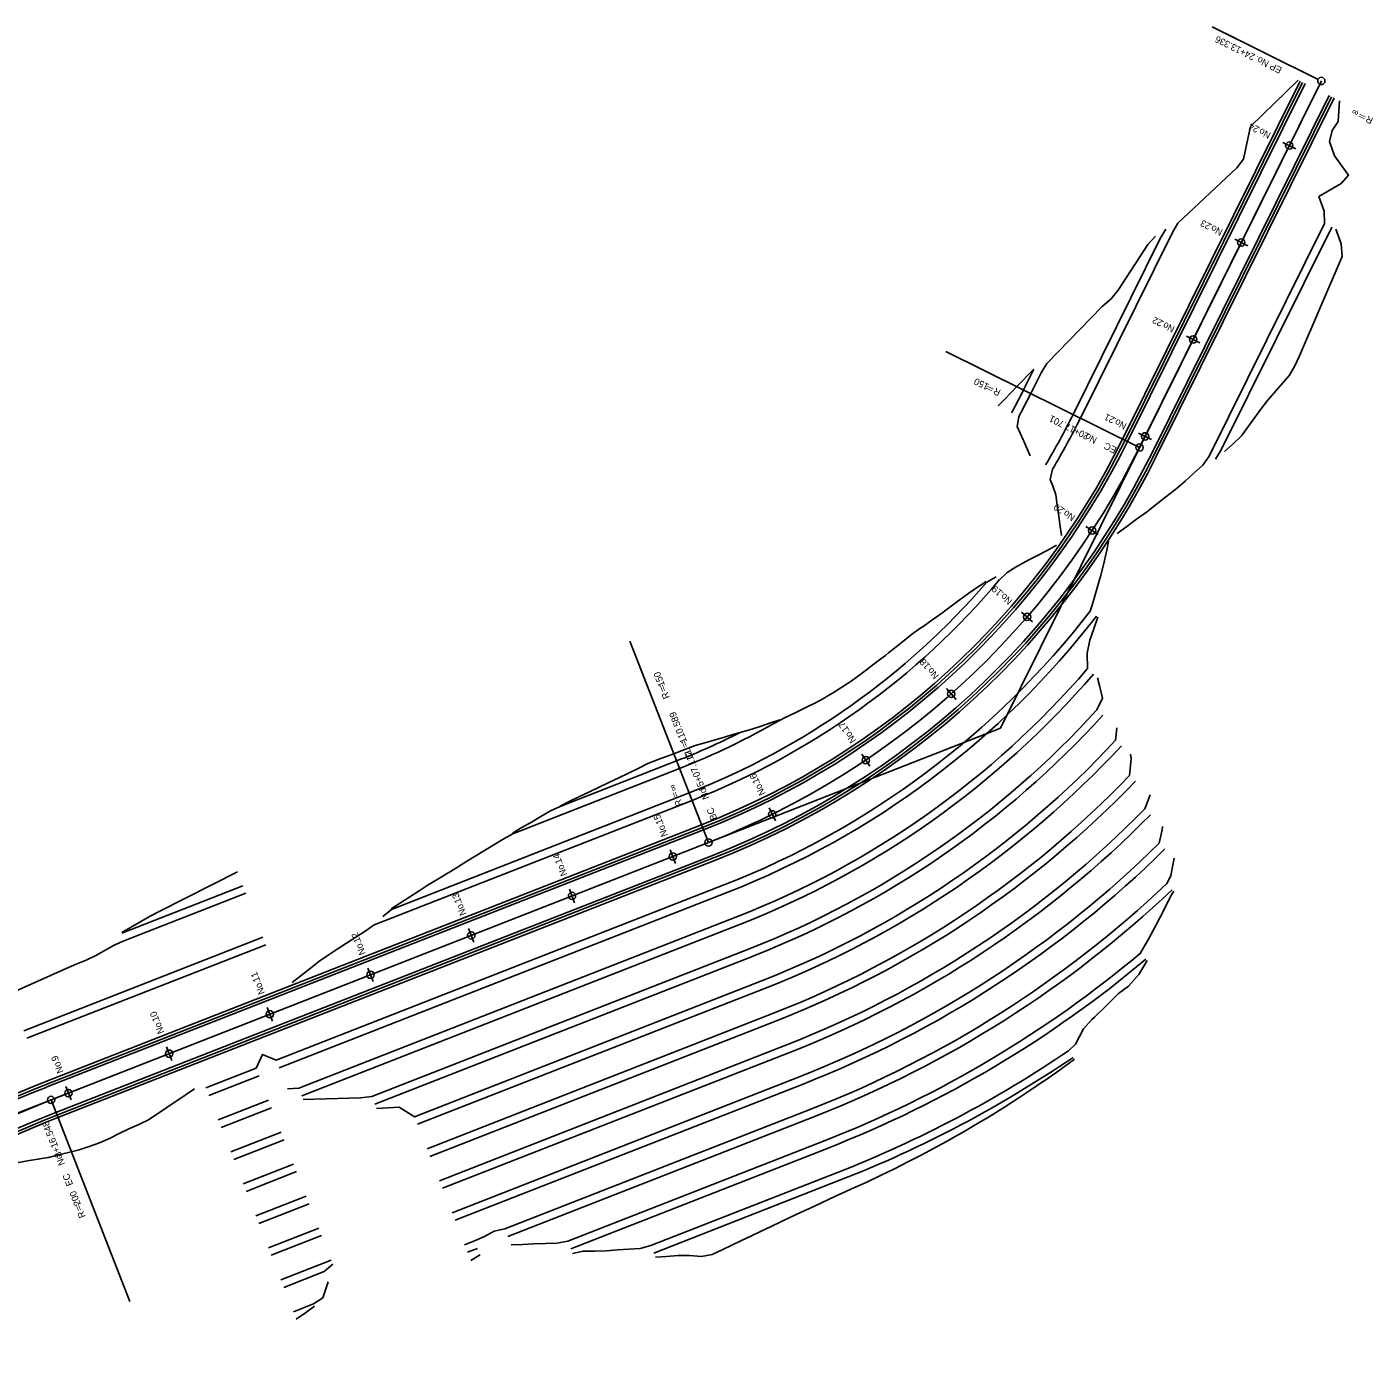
# Model space of a CAD drawing. Extents: x 46571 to 46965, y 10697 to 11034.
# Drawn here: x 46716.5 to 46965.4, y 10784.8 to 11033.7 of the extents above; entities that cross this region are included whole.
import ezdxf

# ---------------------------------------------------------------- set-up
doc = ezdxf.new("R2010")
doc.units = 0
for name, color, linetype in [('Default', 7, 'Continuous'), ('作業レイヤ1', 7, 'Continuous'), ('地形_主曲線_等高線', 7, 'Continuous'), ('地形_土崖 コンクリート、堅固な石積等斜面（地理院地図Vector）', 7, 'Continuous'), ('建物_普通建物_普通建物（地理院地図Vector）', 7, 'Continuous'), ('建物_普通建物_普通建物（外周線）（地理院地図Vector）', 7, 'Continuous'), ('河川_通常部（地理院地図Vector）', 7, 'Continuous'), ('現況_地形_三角形', 7, 'Continuous'), ('等高線等深線_等高線_主曲線通常部（地理院地図Vector）', 7, 'Continuous'), ('道路_通常部_通常部（地理院地図Vector）', 7, 'Continuous')]:
    doc.layers.add(name, color=color, linetype=linetype)

msp = doc.modelspace()

# ---------------------------------------------------------------- linework, layer by layer
at = {"layer": 'Default'}
for p, q in [((46955.22, 11024.01), (46935.66, 11033.7)), ((46935.66, 11033.7), (46940.14, 11031.48)), ((46896.47, 10904.04), (46955.82, 11023.71)), ((46922.21, 10955.95), (46955.82, 11023.71)), ((46955.82, 11023.71), (46955.82, 11023.71)), ((46949.89, 11011.76), (46949.89, 11011.76)), ((46941.01, 10993.84), (46941.01, 10993.84)), ((46932.12, 10975.92), (46932.12, 10975.92)), ((46922.21, 10955.95), (46886.38, 10973.72)), ((46923.23, 10958.01), (46923.23, 10958.01)), ((46922.21, 10955.95), (46922.21, 10955.95)), ((46913.43, 10940.59), (46913.43, 10940.59)), ((46901.41, 10924.62), (46901.41, 10924.62)), ((46842.51, 10882.92), (46827.93, 10920.17)), ((46887.38, 10910.39), (46887.38, 10910.39)), ((46679.76, 10819.21), (46896.47, 10904.04)), ((46871.58, 10898.15), (46871.58, 10898.15)), ((46854.29, 10888.13), (46854.29, 10888.13)), ((46720.93, 10835.33), (46842.51, 10882.92)), ((46842.51, 10882.92), (46842.51, 10882.92)), ((46835.89, 10880.33), (46835.89, 10880.33)), ((46817.26, 10873.04), (46817.26, 10873.04)), ((46798.64, 10865.75), (46798.64, 10865.75)), ((46780.01, 10858.46), (46780.01, 10858.46)), ((46761.39, 10851.17), (46761.39, 10851.17)), ((46742.77, 10843.88), (46742.77, 10843.88)), ((46720.93, 10835.33), (46720.93, 10835.33)), ((46720.93, 10835.33), (46735.51, 10798.08)), ((46724.14, 10836.59), (46724.14, 10836.59))]:
    msp.add_line(p, q, dxfattribs=at)
for centre in [(46955.82, 11023.71), (46949.89, 11011.76), (46941.01, 10993.84), (46932.12, 10975.92), (46923.23, 10958.01), (46922.21, 10955.95), (46913.43, 10940.59), (46901.41, 10924.62), (46887.38, 10910.39), (46871.58, 10898.15), (46854.29, 10888.13), (46842.51, 10882.92), (46835.89, 10880.33), (46817.26, 10873.04), (46798.64, 10865.75), (46780.01, 10858.46), (46761.39, 10851.17), (46742.77, 10843.88), (46720.93, 10835.33), (46724.14, 10836.59)]:
    msp.add_circle(centre, 0.675, dxfattribs=at)
for centre, radius, start, end in [((46787.83, 11022.6), 150, 291.3768, 333.6189), ((46787.83, 11022.6), 150, 291.3768, 333.6189), ((46793.83, 10649.09), 200, 111.3768, 136.3054), ((46793.83, 10649.09), 200, 111.3768, 136.3054)]:
    msp.add_arc(centre, radius, start, end, dxfattribs=at)
at = {"layer": '作業レイヤ1'}
for p, q in [((46922.21, 10955.95), (46955.82, 11023.71)), ((46720.93, 10835.33), (46842.51, 10882.92))]:
    msp.add_line(p, q, dxfattribs=at)
for centre, radius, start, end in [((46787.83, 11022.6), 150, 291.3768, 333.6189), ((46793.83, 10649.09), 200, 111.3768, 136.3054)]:
    msp.add_arc(centre, radius, start, end, dxfattribs=at)
at = {"layer": '地形_主曲線_等高線'}
for p, q in [((46900.75, 10966.59), (46902.66, 10970.45)), ((46734.03, 10866.19), (46756.38, 10874.94)), ((46715.92, 10848.11), (46760.11, 10865.41)), ((46716.47, 10846.72), (46760.66, 10864.01))]:
    msp.add_line(p, q, dxfattribs=at)
for points in [[(46911.26, 10961.38), (46928.27, 10995.69), (46929.31, 10997.41), (46940.19, 11007.64), (46941.42, 11009.27), (46942.28, 11013.3), (46942.72, 11015.32), (46951.52, 11023.87)], [(46918.04, 10940.04), (46919.19, 10940.86), (46919.85, 10941.34), (46921.65, 10942.67), (46923.46, 10944.02), (46925.27, 10945.4), (46927.08, 10946.81), (46927.89, 10947.45), (46928.89, 10948.24), (46930.66, 10949.73), (46932.33, 10951.26), (46933.91, 10952.71), (46935.08, 10954.36), (46956.41, 10997.37), (46956.34, 10999.63), (46955.38, 11002.34), (46959.47, 11004.78), (46960.85, 11006.32), (46958.23, 11009.86), (46957.32, 11012.54), (46957.81, 11014.53), (46958.92, 11016.21), (46959.17, 11020.07)], [(46902.09, 10965.93), (46904, 10969.78), (46905.09, 10971.47), (46915.28, 10982.04), (46916.97, 10983.44), (46918.26, 10985.03), (46923.76, 10993.46), (46925.16, 10995)], [(46909.91, 10962.05), (46926.04, 10994.57), (46927.07, 10996.29)], [(46936.25, 10953.78), (46937.31, 10955.49), (46957.75, 10996.7)], [(46937.94, 10955.18), (46939.52, 10956.63), (46941.07, 10958.09), (46944.66, 10963.01), (46945.87, 10964.64), (46949.96, 10969.31), (46950.92, 10971.07), (46951.77, 10972.87), (46959.7, 10991.27), (46959.47, 10993.61), (46958.48, 10996.34)], [(46896.09, 10963.67), (46896.63, 10964.22), (46897.29, 10964.9), (46898.49, 10966.14), (46899.5, 10967.22), (46902.63, 10970.46)], [(46902, 10954.4), (46900.8, 10957.15), (46900.75, 10957.27), (46899.58, 10959.83), (46899.86, 10961.63)], [(46907.76, 10939.65), (46907.43, 10942.22), (46907.34, 10942.81), (46907.02, 10944.77), (46906.75, 10947.19), (46906.11, 10949.01), (46905.68, 10950.06), (46906.11, 10951.95)], [(46734, 10866.27), (46739.26, 10869.29), (46741.04, 10870.23), (46755.38, 10877.49)], [(46713.25, 10854.95), (46723.72, 10859.62), (46725.55, 10860.42), (46727.4, 10861.18), (46729.22, 10862.02), (46732.73, 10864.03), (46734.58, 10864.79), (46756.93, 10873.54)], [(46714.62, 10823.71), (46716.57, 10824.04), (46718.51, 10824.36), (46719.59, 10824.54), (46720.43, 10824.71), (46722.3, 10825.17), (46724.17, 10825.62), (46724.68, 10825.75), (46726.1, 10826.09), (46728, 10826.74), (46729.89, 10827.4), (46731.71, 10828.22), (46733.51, 10829.12), (46735.32, 10829.98), (46737.14, 10830.81), (46738.96, 10831.66), (46745.76, 10836.22), (46747.45, 10837.38)]]:
    msp.add_lwpolyline(points, dxfattribs=at)
for radius, start in [(126.04, 331.4411), (127.54, 331.4411), (136.27, 329.1493), (137.77, 329.1493)]:
    msp.add_arc((46787.83, 11022.6), radius, start, 333.6189, dxfattribs=at)
at = {"layer": '地形_土崖 コンクリート、堅固な石積等斜面（地理院地図Vector）'}
for p, q in [((46919.53, 10957.28), (46952.35, 11023.46)), ((46924.9, 10954.61), (46957.72, 11020.79)), ((46719.83, 10838.12), (46841.42, 10885.71)), ((46722.02, 10832.53), (46843.6, 10880.12))]:
    msp.add_line(p, q, dxfattribs=at)
for centre, radius, start, end in [((46787.83, 11022.6), 147, 291.3768, 333.6189), ((46787.83, 11022.6), 153, 291.3768, 333.6189), ((46793.83, 10649.09), 203, 111.3768, 136.3054), ((46793.83, 10649.09), 197, 111.3768, 136.3054)]:
    msp.add_arc(centre, radius, start, end, dxfattribs=at)
at = {"layer": '建物_普通建物_普通建物（地理院地図Vector）'}
for p, q in [((46919.97, 10957.06), (46952.8, 11023.24)), ((46924.45, 10954.84), (46957.28, 11021.01)), ((46720.02, 10837.66), (46841.6, 10885.25)), ((46721.84, 10833), (46843.42, 10880.59))]:
    msp.add_line(p, q, dxfattribs=at)
for centre, radius, start, end in [((46787.83, 11022.6), 147.5, 291.3768, 333.6189), ((46787.83, 11022.6), 152.5, 291.3768, 333.6189), ((46793.83, 10649.09), 202.5, 111.3768, 136.3054), ((46793.83, 10649.09), 197.5, 111.3768, 136.3054)]:
    msp.add_arc(centre, radius, start, end, dxfattribs=at)
at = {"layer": '建物_普通建物_普通建物（外周線）（地理院地図Vector）'}
for p, q in [((46919.08, 10957.5), (46951.9, 11023.68)), ((46925.35, 10954.39), (46958.17, 11020.57)), ((46719.65, 10838.59), (46841.23, 10886.18)), ((46722.2, 10832.07), (46843.78, 10879.66))]:
    msp.add_line(p, q, dxfattribs=at)
for centre, radius, start, end in [((46787.83, 11022.6), 146.5, 291.3768, 333.6189), ((46787.83, 11022.6), 153.5, 291.3768, 333.6189), ((46793.83, 10649.09), 203.5, 111.3768, 136.3054), ((46793.83, 10649.09), 196.5, 111.3768, 136.3054)]:
    msp.add_arc(centre, radius, start, end, dxfattribs=at)
at = {"layer": '現況_地形_三角形'}
for p, q in [((46893.96, 10931.06), (46895.7, 10932.03)), ((46917.76, 10901.81), (46918.02, 10904.1)), ((46923.19, 10889.12), (46924.15, 10891.71)), ((46763.12, 10841.26), (46846.1, 10873.75)), ((46767.3, 10836.08), (46848.41, 10867.83)), ((46780.78, 10834.54), (46850.73, 10861.92)), ((46788.69, 10830.82), (46853.04, 10856.01)), ((46790.45, 10826.3), (46854.81, 10851.49)), ((46791, 10824.9), (46855.36, 10850.09)), ((46792.77, 10820.39), (46857.13, 10845.58)), ((46793.32, 10818.99), (46857.67, 10844.18)), ((46750.08, 10836.16), (46759.39, 10839.81)), ((46795.08, 10814.47), (46859.44, 10839.66)), ((46795.63, 10813.08), (46859.99, 10838.27)), ((46751.85, 10831.65), (46761.16, 10835.29)), ((46752.4, 10830.25), (46761.71, 10833.89)), ((46805.39, 10810.08), (46862.3, 10832.35)), ((46754.16, 10825.73), (46763.48, 10829.38)), ((46754.71, 10824.34), (46764.02, 10827.98)), ((46817.02, 10807.81), (46864.62, 10826.44)), ((46756.48, 10819.82), (46765.79, 10823.46)), ((46757.03, 10818.42), (46766.34, 10822.07)), ((46832.37, 10807), (46866.93, 10820.53)), ((46758.79, 10813.91), (46768.1, 10817.55)), ((46759.34, 10812.51), (46768.65, 10816.15)), ((46761.11, 10807.99), (46770.42, 10811.64)), ((46761.65, 10806.6), (46770.97, 10810.24)), ((46763.42, 10802.08), (46772.73, 10805.72)), ((46797.94, 10807.16), (46799.81, 10807.89)), ((46798.53, 10805.67), (46800.28, 10806.68))]:
    msp.add_line(p, q, dxfattribs=at)
for points in [[(46896.32, 10931.51), (46897.7, 10932.82), (46899.38, 10933.9), (46901.19, 10934.9), (46901.99, 10935.32), (46903.07, 10935.88), (46904.97, 10936.87), (46906.55, 10937.72), (46906.87, 10937.9)], [(46913.08, 10925.71), (46913.38, 10926.61), (46913.76, 10927.84), (46914.39, 10929.98), (46914.89, 10931.76), (46914.99, 10932.12), (46915.53, 10934.28), (46916.02, 10936.44), (46916.13, 10936.94), (46916.48, 10938.6)], [(46855.73, 10905.57), (46856.66, 10906.03), (46857.36, 10906.36), (46858.99, 10907.14), (46860.63, 10907.94), (46862.26, 10908.76), (46863.87, 10909.61), (46864.47, 10909.98), (46865.42, 10910.56), (46866.96, 10911.53), (46868.18, 10912.3), (46868.5, 10912.51), (46869.98, 10913.57), (46871.45, 10914.65), (46871.73, 10914.86), (46872.9, 10915.74), (46874.35, 10916.85), (46875.21, 10917.51), (46875.79, 10917.97), (46877.22, 10919.1), (46878.65, 10920.24), (46880.06, 10921.4), (46881.57, 10922.46), (46882.18, 10922.88), (46883.09, 10923.51), (46884.6, 10924.59), (46885.83, 10925.47), (46886.11, 10925.68), (46887.62, 10926.78), (46889.12, 10927.9), (46889.44, 10928.14), (46890.63, 10929.03), (46892.22, 10930.1), (46893.2, 10930.77), (46893.8, 10931.19)], [(46912.55, 10915.02), (46912.52, 10917.91), (46913.03, 10920.3), (46913.78, 10922.45), (46914.5, 10924.61)], [(46914.33, 10907.46), (46915.36, 10909.59), (46914.8, 10911.94), (46914.45, 10913.37)], [(46848.34, 10903.26), (46848.76, 10903.36), (46850.51, 10903.85), (46852.24, 10904.43), (46853.97, 10905.02), (46855.7, 10905.61)], [(46815.05, 10889.67), (46816.85, 10890.54), (46818.66, 10891.41), (46820.47, 10892.27), (46822.28, 10893.14), (46824.09, 10894.01), (46825.89, 10894.88), (46827.7, 10895.75), (46829.51, 10896.62), (46831.31, 10897.51), (46833.17, 10898.24), (46835.04, 10898.94), (46836.08, 10899.34), (46836.81, 10899.62), (46838.46, 10900.25), (46840.04, 10900.86), (46841.83, 10901.36), (46843.56, 10901.85), (46844.18, 10902.03), (46845.28, 10902.35), (46847.01, 10902.87), (46848.33, 10903.28)], [(46806.27, 10884.67), (46808.01, 10885.69), (46809.76, 10886.71), (46811.51, 10887.73), (46813.26, 10888.76), (46815.08, 10889.58), (46836.6, 10898)], [(46920.37, 10895.33), (46920.64, 10898.44), (46920.5, 10899.27)], [(46783.83, 10870.65), (46785.54, 10871.77), (46787.25, 10872.89), (46788.97, 10873.99), (46790.68, 10875.09), (46792.42, 10876.15), (46794.15, 10877.2), (46795.89, 10878.26), (46797.62, 10879.32), (46799.36, 10880.37), (46801.09, 10881.43), (46802.82, 10882.49), (46804.55, 10883.55), (46806.32, 10884.54), (46837.15, 10896.61)], [(46765.54, 10857.04), (46767.18, 10858.32), (46768.82, 10859.61), (46770.47, 10860.9), (46772.15, 10862.09), (46773.86, 10863.21), (46775.57, 10864.32), (46777.28, 10865.44), (46778.99, 10866.56), (46780.7, 10867.69), (46782.56, 10868.42), (46839.47, 10890.69)], [(46782.25, 10869.22), (46783.87, 10870.54), (46838.92, 10892.09)], [(46925.86, 10882.8), (46926.41, 10885.24), (46926.46, 10885.89)], [(46927.22, 10875.29), (46927.96, 10876.83), (46928.63, 10880)], [(46749.53, 10837.56), (46758.85, 10841.2), (46760.01, 10843.73), (46762.57, 10842.66), (46845.55, 10875.14)], [(46922.41, 10862.5), (46923.87, 10865.08), (46925.27, 10867.69), (46926.62, 10870.31), (46927.94, 10872.91), (46928.52, 10873.92)], [(46764.63, 10837.41), (46766.75, 10837.48), (46847.87, 10869.23)], [(46767.56, 10835.41), (46776.06, 10835.64), (46778.18, 10835.7), (46780.24, 10835.94), (46850.18, 10863.32)], [(46909.07, 10844.43), (46910.39, 10845.63), (46911.87, 10848.5), (46913.41, 10850.19), (46913.85, 10850.61), (46915.91, 10852.6), (46917.93, 10854.64), (46918.34, 10854.99), (46920.16, 10856.38), (46922.09, 10858.5), (46922.99, 10860.05), (46923.59, 10861.1)], [(46781.09, 10833.77), (46783.21, 10833.84), (46785.3, 10833.98), (46788.14, 10832.21), (46852.5, 10857.4)], [(46832.67, 10806.25), (46834.76, 10806.39), (46836.85, 10806.54), (46838.99, 10806.54), (46841.21, 10806.38), (46843.2, 10806.78), (46845.01, 10807.64), (46846.82, 10808.5), (46848.63, 10809.36), (46850.44, 10810.22), (46852.25, 10811.08), (46854.07, 10811.93), (46855.88, 10812.78), (46857.69, 10813.64), (46859.51, 10814.49), (46861.32, 10815.34), (46863.14, 10816.19), (46864.96, 10817.03), (46866.77, 10817.88), (46867.78, 10818.35), (46868.97, 10818.88), (46871.63, 10820.09), (46874.17, 10821.29), (46874.28, 10821.34), (46876.91, 10822.62), (46879.51, 10823.93), (46880.46, 10824.42), (46882.1, 10825.27), (46884.68, 10826.65), (46886.64, 10827.73), (46887.23, 10828.06), (46889.76, 10829.51), (46892.27, 10830.98), (46892.7, 10831.24), (46894.25, 10832.17), (46894.76, 10832.48), (46897.23, 10834.02), (46898.65, 10834.92), (46899.68, 10835.59), (46902.11, 10837.19), (46904.47, 10838.79), (46904.51, 10838.82), (46906.89, 10840.49), (46909.25, 10842.18), (46910.15, 10842.84)], [(46797.4, 10808.56), (46799.26, 10809.29), (46801.1, 10810.07), (46802.85, 10811.08), (46804.85, 10811.48), (46861.75, 10833.75)], [(46806, 10808.52), (46808.12, 10808.61), (46810.23, 10808.7), (46812.35, 10808.78), (46814.46, 10808.86), (46816.47, 10809.21), (46864.07, 10827.84)], [(46817.37, 10806.91), (46819.35, 10807.34), (46821.48, 10807.38), (46823.61, 10807.44), (46825.7, 10807.59), (46827.79, 10807.74), (46829.88, 10807.89), (46831.83, 10808.4), (46866.38, 10821.92)], [(46763.97, 10800.68), (46771.42, 10803.6), (46773.03, 10804.96)], [(46765.74, 10796.17), (46769.46, 10797.62), (46771.16, 10798.77), (46772.16, 10801.7)], [(46766.28, 10794.77), (46767.97, 10795.95), (46769.63, 10797.2)]]:
    msp.add_lwpolyline(points, dxfattribs=at)
for radius, end in [(140.15, 319.218), (141.65, 319.982), (158.35, 322.2738), (159.85, 322.2738), (164.7, 319.218), (166.2, 319.218), (135.3, 300.1195), (171.05, 317.6902), (172.55, 317.6902), (133.8, 296.8866), (177.4, 317.0894), (178.9, 317.0894), (183.75, 316.1623), (185.25, 316.1623), (190.1, 315.3983), (191.6, 315.3983), (196.45, 314.6344), (197.95, 314.6344), (202.8, 313.4161), (204.3, 313.4161), (209.15, 310.0507), (210.65, 310.0507), (215.5, 304.2331), (217, 304.2331)]:
    msp.add_arc((46787.83, 11022.6), radius, 291.3768, end, dxfattribs=at)
at = {"layer": '等高線等深線_等高線_主曲線通常部（地理院地図Vector）'}
for p, q in [((46922.21, 10955.95), (46955.82, 11023.71)), ((46720.93, 10835.33), (46842.51, 10882.92))]:
    msp.add_line(p, q, dxfattribs=at)
for centre, radius, start, end in [((46787.83, 11022.6), 150, 291.3768, 333.6189), ((46793.83, 10649.09), 200, 111.3768, 136.3054)]:
    msp.add_arc(centre, radius, start, end, dxfattribs=at)
at = {"layer": '道路_通常部_通常部（地理院地図Vector）'}
for p, q in [((46948.69, 11012.36), (46951.1, 11011.16)), ((46939.8, 10994.44), (46942.22, 10993.24)), ((46930.91, 10976.52), (46933.33, 10975.32)), ((46922.02, 10958.61), (46924.44, 10957.41)), ((46912.3, 10941.33), (46914.56, 10939.85)), ((46900.39, 10925.5), (46902.44, 10923.74)), ((46886.49, 10911.4), (46888.28, 10909.38)), ((46870.83, 10899.27), (46872.33, 10897.03)), ((46853.7, 10889.34), (46854.89, 10886.92)), ((46835.39, 10881.58), (46836.38, 10879.07)), ((46816.77, 10874.29), (46817.75, 10871.78)), ((46798.15, 10867), (46799.13, 10864.49)), ((46779.52, 10859.71), (46780.51, 10857.2)), ((46760.9, 10852.42), (46761.88, 10849.91)), ((46742.27, 10845.13), (46743.26, 10842.62)), ((46723.65, 10837.84), (46724.63, 10835.33))]:
    msp.add_line(p, q, dxfattribs=at)

# ---------------------------------------------------------------- texts
at = {"layer": 'Default'}
for s, rotation, p in [('24+13.336', 153.6189, (46943.69, 11028.58)), ('EP No.', 153.6189, (46948.65, 11026.12)), ('R＝∞', 153.6189, (46965.51, 11016.81)), ('150', 153.6189, (46894.48, 10967.61)), ('R＝', 153.6189, (46896.66, 10966.53)), ('20+17.701', 153.6189, (46913.01, 10958.42)), ('EC\u3000No.', 153.6189, (46918.1, 10955.89)), ('150', 111.3768, (46834.47, 10912.02)), ('R＝', 111.3768, (46835.36, 10909.75)), ('110.589', 111.3768, (46838.56, 10901.59)), ('CL＝', 111.3768, (46839.74, 10898.57)), ('15+07.112', 111.3768, (46842.05, 10892.65)), ('R＝∞', 111.3768, (46837.75, 10889.92)), ('BC\u3000No.', 111.3768, (46844.13, 10887.36)), ('8+16.548', 111.3768, (46722.96, 10824.99)), ('EC\u3000No.', 111.3768, (46725.03, 10819.7)), ('200', 111.3768, (46726.46, 10816.05)), ('R＝', 111.3768, (46727.35, 10813.78))]:
    msp.add_text(s, height=1.25, rotation=rotation, dxfattribs=at).set_placement(p)
at = {"layer": '河川_通常部（地理院地図Vector）'}
for s, rotation, p in [('24', 153.6189, (46944.41, 11015.18)), ('No.', 153.6189, (46946.59, 11014.1)), ('23', 153.6189, (46935.52, 10997.26)), ('No.', 153.6189, (46937.7, 10996.18)), ('22', 153.6189, (46926.63, 10979.34)), ('No.', 153.6189, (46928.82, 10978.26)), ('21', 153.6189, (46917.75, 10961.43)), ('No.', 153.6189, (46919.93, 10960.34)), ('20', 146.8575, (46908.38, 10944.63)), ('No.', 146.8575, (46910.42, 10943.3)), ('19', 139.218, (46896.95, 10929.3)), ('No.', 139.218, (46898.79, 10927.71)), ('18', 131.5786, (46883.58, 10915.62)), ('No.', 131.5786, (46885.19, 10913.8)), ('17', 123.9392, (46868.51, 10903.84)), ('No.', 123.9392, (46869.87, 10901.82)), ('16', 116.2997, (46852, 10894.17)), ('No.', 116.2997, (46853.08, 10891.99)), ('15', 111.3768, (46834.12, 10886.55)), ('No.', 111.3768, (46835.01, 10884.28)), ('14', 111.3768, (46815.5, 10879.26)), ('No.', 111.3768, (46816.39, 10876.99)), ('13', 111.3768, (46796.87, 10871.97)), ('No.', 111.3768, (46797.76, 10869.7)), ('12', 111.3768, (46778.25, 10864.68)), ('No.', 111.3768, (46779.14, 10862.41)), ('11', 111.3768, (46759.63, 10857.39)), ('No.', 111.3768, (46760.51, 10855.12)), ('10', 111.3768, (46741, 10850.1)), ('No.', 111.3768, (46741.89, 10847.83)), ('9', 111.3768, (46722.38, 10842.81)), ('No.', 111.3768, (46723.27, 10840.54))]:
    msp.add_text(s, height=1.25, rotation=rotation, dxfattribs=at).set_placement(p)

doc.saveas('drawing.dxf')
